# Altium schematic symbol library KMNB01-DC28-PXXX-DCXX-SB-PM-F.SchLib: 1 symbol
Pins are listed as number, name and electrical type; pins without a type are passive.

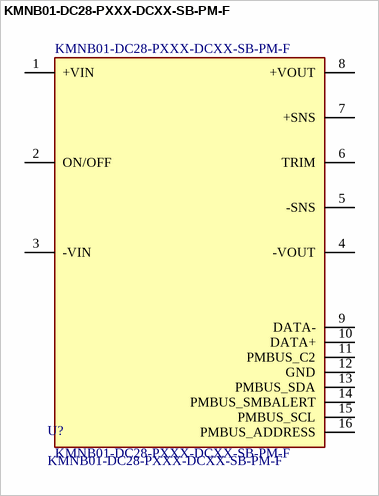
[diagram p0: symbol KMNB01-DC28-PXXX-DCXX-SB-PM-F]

## KMNB01-DC28-PXXX-DCXX-SB-PM-F
designator U?
16-40Vin XXVout XXXW Nonisolated Sixteenth Brick with Flanged Option; MFG: KOLT
footprint KMNB01-DC28-PXXX-DCXX-SB-PM-F
pins: 1 +VIN, 2 ON/OFF, 3 -VIN, 4 -VOUT, 5 -SNS, 6 TRIM, 7 +SNS, 8 +VOUT, 9 DATA-, 10 DATA+, 11 PMBUS_C2, 12 GND, 13 PMBUS_SDA, 14 PMBUS_SMBALERT, 15 PMBUS_SCL, 16 PMBUS_ADDRESS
